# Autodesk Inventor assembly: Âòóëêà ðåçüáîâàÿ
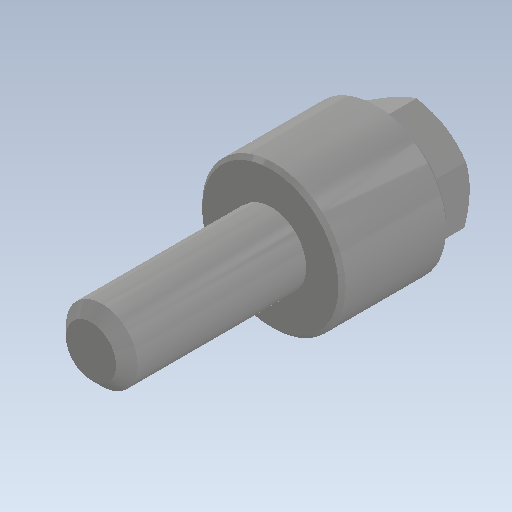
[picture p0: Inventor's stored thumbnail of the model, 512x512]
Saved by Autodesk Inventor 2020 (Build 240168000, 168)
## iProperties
Created: 1900-01
Part Number: Âòóëêà ðåçüáîâàÿ
Document SubType Name: Assembly
Designer: bruno
Author: bruno
Revision Number: ANYUNSPECIFIED
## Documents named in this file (3)
- C:\Users\bruno\Downloads\Âòóëêà ðåçüáîâàÿ.iam
- C:\Users\bruno\Downloads\Áîëò Ì10x1-6gx40 ÃÎÑÒ 7796-70.ipt
- C:\Users\bruno\Downloads\Pièce88.ipt
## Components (2 placed, 2 different names)
1. 9
2. Pièce88
